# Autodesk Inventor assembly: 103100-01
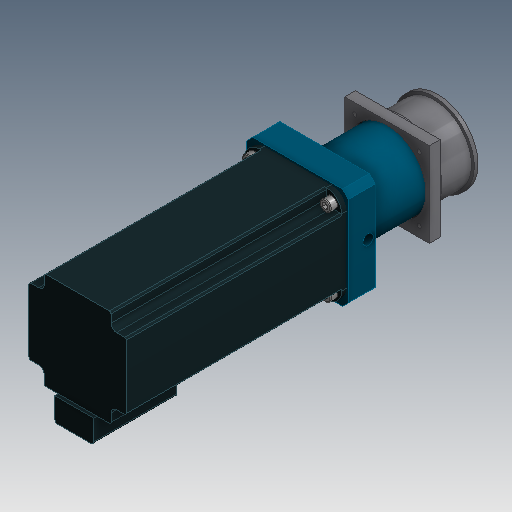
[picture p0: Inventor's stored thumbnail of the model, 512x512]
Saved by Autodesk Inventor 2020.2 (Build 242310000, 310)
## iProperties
Created: 2000-10
Part Number: 103100-01
Document SubType Name: Assembly
Designer: wymerj
Mass: 34733 g
Surface Area: 3117.28 cm^2
Volume: 4432.07 cm^3
Density: 7.83676 g/cm^3
Control State: 0
Master: False
Checked Out: False
Shininess: 0.0
Length Units: 11269
Angle Units: 11279
Time Units: 11290
Mass Units: 11283
Length Display Precision: 3
Angle Display Precision: 2
Compacted: True
Dimensions: 149,1x429,6x128,3 mm
Mass: 34,733 kg
DocNumber: 103100-01.iam
Folder: 01 - Themengebiete\Simplification\01 - Packaging machine\
VDS_Category: 3D Komponenten
Density: 0.0
Volumn: 0.0
Area: 0.0
PropertySet Name: Model Information
Author: wymerj
Revision Number: -
Title: 103100-01
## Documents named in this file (9)
- D:\07 - DEMODATEN\OTX 2019 - Dataset - UPDATE - Dez2019\Designs\07-Packing machine\103100-01.iam
- D:\07 - DEMODATEN\OTX 2019 - Dataset - UPDATE - Dez2019\Designs\07-Packing machine\Parts\ADSK-011811.ipt
- D:\07 - DEMODATEN\OTX 2019 - Dataset - UPDATE - Dez2019\Designs\07-Packing machine\A103445.iam
- D:\07 - DEMODATEN\OTX 2019 - Dataset - UPDATE - Dez2019\Designs\07-Packing machine\Parts\ADSK-011469.ipt
- D:\07 - DEMODATEN\OTX 2019 - Dataset - UPDATE - Dez2019\Designs\07-Packing machine\Parts\ADSK-011781.ipt
- D:\07 - DEMODATEN\OTX 2019 - Dataset - UPDATE - Dez2019\Content Center Files\de-DE\ISO 4762(2)\ISO 4762 - M8 x 25ISO.ipt
- D:\07 - DEMODATEN\OTX 2019 - Dataset - UPDATE - Dez2019\Designs\07-Packing machine\Parts\ADSK-011777.ipt
- D:\07 - DEMODATEN\OTX 2019 - Dataset - UPDATE - Dez2019\Content Center Files\de-DE\ISO 2338(2)\ISO 2338 - 10 m6 x 18.ipt
- D:\07 - DEMODATEN\OTX 2019 - Dataset - UPDATE - Dez2019\Content Center Files\de-DE\ISO 4026\ISO 4026 - M8 x 16 - ISO.ipt
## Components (12 placed, 8 different names)
1. ADSK-011811:1 — Insert:1, Mate:1, Insert:2, Mate:4, Passend:5
2. A103445:1 [sub-assembly] — Insert:1, Mate:1
3. ADSK-011469:1 — Insert:2, Passend:3, Passend:5
4. ADSK-011781:1 — Passend:3, Mate:4, Passend:6, Passend:7, Einfügen:7, Einfügen:8, Einfügen:9
5. ISO 4762 M8 x 25:1
6. ISO 4762 M8 x 25:2
7. ISO 4762 M8 x 25:3
8. ISO 4762 M8 x 25:4
9. ADSK-011777:1 — Passend:6, Passend:7
10. ISO 2338 10 m6 x 18:1 — Einfügen:7
11. ISO 4026 M8 x 16:1 — Einfügen:9
12. ISO 2338 10 m6 x 18:2 — Einfügen:8
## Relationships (11: Mate 6, Insert 5)
- Insert:1: ADSK-011811:1 ↔ A103445:1
- Mate:1: ADSK-011811:1 ↔ A103445:1
- Insert:2: ADSK-011811:1 ↔ ADSK-011469:1
- Passend:3 [Mate]: ADSK-011469:1 ↔ ADSK-011781:1
- Mate:4: ADSK-011811:1 ↔ ADSK-011781:1
- Passend:5 [Mate]: ADSK-011811:1 ↔ ADSK-011469:1
- Passend:6 [Mate]: ADSK-011781:1 ↔ ADSK-011777:1
- Passend:7 [Mate]: ADSK-011781:1 ↔ ADSK-011777:1
- Einfügen:7 [Insert]: ADSK-011781:1 ↔ ISO 2338 10 m6 x 18:1
- Einfügen:8 [Insert]: ADSK-011781:1 ↔ ISO 2338 10 m6 x 18:2
- Einfügen:9 [Insert]: ADSK-011781:1 ↔ ISO 4026 M8 x 16:1
